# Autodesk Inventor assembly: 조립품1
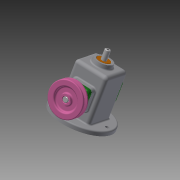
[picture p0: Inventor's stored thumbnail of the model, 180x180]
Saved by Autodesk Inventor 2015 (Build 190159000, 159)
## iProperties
Created: 2021-08
Part Number: 조립품1
Document SubType Name: Assembly
Designer: 10415
Author: 10415
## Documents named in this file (16)
- C:\Users\10415\Desktop\710806V1016\조립품1.iam
- C:\Users\10415\Desktop\710806V1016\V벨트풀리.ipt
- C:\Users\10415\Desktop\710806V1016\고정핀 1.2x8.ipt
- C:\Users\10415\Desktop\710806V1016\뒤커버.ipt
- C:\Users\10415\Desktop\710806V1016\링크.ipt
- C:\Users\10415\Desktop\710806V1016\멈춤나사 M3x8.ipt
- C:\Users\10415\Desktop\710806V1016\베어링 12x32x10.ipt
- C:\Users\10415\Desktop\710806V1016\본체.ipt
- C:\Users\10415\Desktop\710806V1016\볼트 M4.ipt
- C:\Users\10415\Desktop\710806V1016\부시.ipt
- C:\Users\10415\Desktop\710806V1016\슬라이드.ipt
- C:\Users\10415\Desktop\710806V1016\앞커버.ipt
- C:\Users\10415\Desktop\710806V1016\오일 실 12 25 7.ipt
- C:\Users\10415\Desktop\710806V1016\키 4x4x10.ipt
- C:\Users\10415\Desktop\710806V1016\편심축.ipt
- C:\Users\10415\Desktop\710806V1016\핀 5x18.ipt
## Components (3 placed, 3 different names)
1. V벨트풀리:1 — 각도:2
2. 고정핀 1.2x8:1
3. 핀 5x18:1
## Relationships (1: Angle 1)
- 각도:2 [Angle]: V벨트풀리:1
